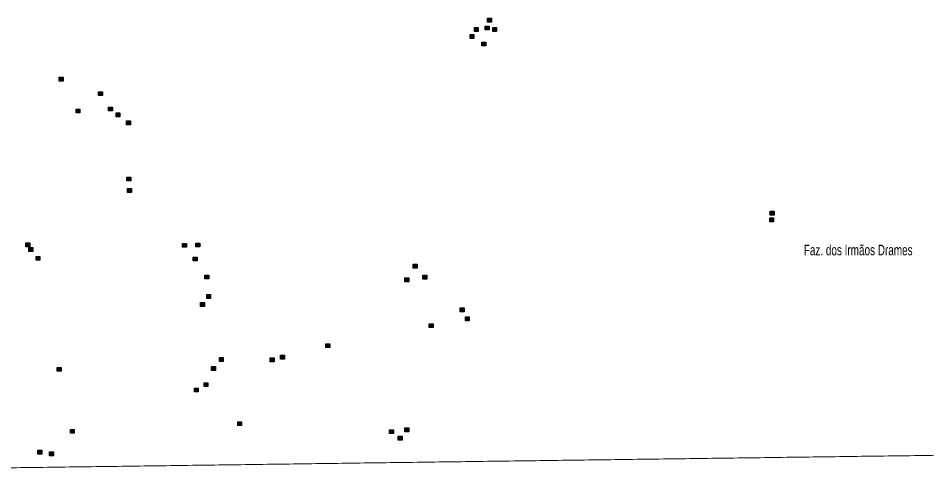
# Model space of a CAD drawing. Extents: x 265.7 to 292.1, y 7676.2 to 7704.2.
# Drawn here: x 272.68 to 279.53, y 7676.18 to 7679.65 of the extents above; entities that cross this region are included whole.
import ezdxf

# ---------------------------------------------------------------- set-up
doc = ezdxf.new("R2010")
doc.units = 0
doc.header["$LTSCALE"] = 0.032
doc.layers.add('2', color=7, linetype='Continuous', lineweight=25)
doc.layers.add('63', color=7, linetype='Continuous', lineweight=13)
doc.layers.add('61', color=7, linetype='Continuous')

msp = doc.modelspace()

# ---------------------------------------------------------------- hatches: boundary and pattern name
at = {"layer": '2'}
for points in [[(276.2203, 7679.6541), (276.2493, 7679.6541), (276.2493, 7679.6251), (276.2203, 7679.6251)], [(276.1216, 7679.5829), (276.1506, 7679.5829), (276.1506, 7679.5539), (276.1216, 7679.5539)], [(276.2036, 7679.5951), (276.2326, 7679.5951), (276.2326, 7679.5661), (276.2036, 7679.5661)], [(276.2597, 7679.5838), (276.2887, 7679.5838), (276.2887, 7679.5548), (276.2597, 7679.5548)], [(276.0885, 7679.5312), (276.1175, 7679.5312), (276.1175, 7679.5022), (276.0885, 7679.5022)], [(276.1781, 7679.474), (276.2071, 7679.474), (276.2071, 7679.445), (276.1781, 7679.445)], [(272.9935, 7679.2092), (273.0225, 7679.2092), (273.0225, 7679.1802), (272.9935, 7679.1802)], [(273.2897, 7679.1003), (273.3187, 7679.1003), (273.3187, 7679.0713), (273.2897, 7679.0713)], [(273.1194, 7678.9688), (273.1484, 7678.9688), (273.1484, 7678.9398), (273.1194, 7678.9398)], [(273.3648, 7678.984), (273.3938, 7678.984), (273.3938, 7678.955), (273.3648, 7678.955)], [(273.4212, 7678.9405), (273.4502, 7678.9405), (273.4502, 7678.9115), (273.4212, 7678.9115)], [(273.5003, 7678.8807), (273.5293, 7678.8807), (273.5293, 7678.8517), (273.5003, 7678.8517)], [(273.5036, 7678.4571), (273.5326, 7678.4571), (273.5326, 7678.4281), (273.5036, 7678.4281)], [(273.5085, 7678.3699), (273.5375, 7678.3699), (273.5375, 7678.3409), (273.5085, 7678.3409)], [(278.3507, 7678.1997), (278.3797, 7678.1997), (278.3797, 7678.1707), (278.3507, 7678.1707)], [(278.3466, 7678.1488), (278.3756, 7678.1488), (278.3756, 7678.1198), (278.3466, 7678.1198)], [(272.7417, 7677.9608), (272.7707, 7677.9608), (272.7707, 7677.9318), (272.7417, 7677.9318)], [(272.7644, 7677.926), (272.7934, 7677.926), (272.7934, 7677.897), (272.7644, 7677.897)], [(273.9225, 7677.9575), (273.9515, 7677.9575), (273.9515, 7677.9285), (273.9225, 7677.9285)], [(274.0224, 7677.9601), (274.0514, 7677.9601), (274.0514, 7677.9311), (274.0224, 7677.9311)], [(272.8184, 7677.8591), (272.8474, 7677.8591), (272.8474, 7677.8301), (272.8184, 7677.8301)], [(274.0032, 7677.8543), (274.0322, 7677.8543), (274.0322, 7677.8253), (274.0032, 7677.8253)], [(275.6609, 7677.801), (275.6899, 7677.801), (275.6899, 7677.772), (275.6609, 7677.772)], [(274.0902, 7677.7187), (274.1192, 7677.7187), (274.1192, 7677.6897), (274.0902, 7677.6897)], [(275.598, 7677.6977), (275.627, 7677.6977), (275.627, 7677.6687), (275.598, 7677.6687)], [(275.7334, 7677.717), (275.7624, 7677.717), (275.7624, 7677.688), (275.7334, 7677.688)], [(274.1049, 7677.5717), (274.1339, 7677.5717), (274.1339, 7677.5427), (274.1049, 7677.5427)], [(274.0579, 7677.5113), (274.0869, 7677.5113), (274.0869, 7677.4823), (274.0579, 7677.4823)], [(276.0145, 7677.4718), (276.0435, 7677.4718), (276.0435, 7677.4428), (276.0145, 7677.4428)], [(276.0531, 7677.4031), (276.0821, 7677.4031), (276.0821, 7677.3741), (276.0531, 7677.3741)], [(275.7811, 7677.3522), (275.8101, 7677.3522), (275.8101, 7677.3232), (275.7811, 7677.3232)], [(275.0022, 7677.2012), (275.0312, 7677.2012), (275.0312, 7677.1722), (275.0022, 7677.1722)], [(274.2001, 7677.0972), (274.2291, 7677.0972), (274.2291, 7677.0682), (274.2001, 7677.0682)], [(274.5827, 7677.0955), (274.6117, 7677.0955), (274.6117, 7677.0665), (274.5827, 7677.0665)], [(274.6602, 7677.1143), (274.6892, 7677.1143), (274.6892, 7677.0853), (274.6602, 7677.0853)], [(272.9782, 7677.023), (273.0072, 7677.023), (273.0072, 7676.994), (272.9782, 7676.994)], [(274.1404, 7677.0294), (274.1694, 7677.0294), (274.1694, 7677.0004), (274.1404, 7677.0004)], [(274.0838, 7676.9073), (274.1128, 7676.9073), (274.1128, 7676.8783), (274.0838, 7676.8783)], [(274.012, 7676.8672), (274.041, 7676.8672), (274.041, 7676.8382), (274.012, 7676.8382)], [(274.338, 7676.6139), (274.367, 7676.6139), (274.367, 7676.5849), (274.338, 7676.5849)], [(273.0774, 7676.5566), (273.1064, 7676.5566), (273.1064, 7676.5276), (273.0774, 7676.5276)], [(275.4825, 7676.5532), (275.5115, 7676.5532), (275.5115, 7676.5242), (275.4825, 7676.5242)], [(275.5979, 7676.5678), (275.6269, 7676.5678), (275.6269, 7676.5388), (275.5979, 7676.5388)], [(275.5478, 7676.5048), (275.5768, 7676.5048), (275.5768, 7676.4758), (275.5478, 7676.4758)], [(272.8321, 7676.3999), (272.8611, 7676.3999), (272.8611, 7676.3709), (272.8321, 7676.3709)], [(272.92, 7676.3861), (272.949, 7676.3861), (272.949, 7676.3571), (272.92, 7676.3571)]]:
    msp.add_hatch(color=256, dxfattribs=at).paths.add_polyline_path(points)

# ---------------------------------------------------------------- linework, layer by layer
for points in [[(276.2203, 7679.6541), (276.2493, 7679.6541), (276.2493, 7679.6251), (276.2203, 7679.6251)], [(276.1216, 7679.5829), (276.1506, 7679.5829), (276.1506, 7679.5539), (276.1216, 7679.5539)], [(276.2036, 7679.5951), (276.2326, 7679.5951), (276.2326, 7679.5661), (276.2036, 7679.5661)], [(276.2597, 7679.5838), (276.2887, 7679.5838), (276.2887, 7679.5548), (276.2597, 7679.5548)], [(276.0885, 7679.5312), (276.1175, 7679.5312), (276.1175, 7679.5022), (276.0885, 7679.5022)], [(276.1781, 7679.474), (276.2071, 7679.474), (276.2071, 7679.445), (276.1781, 7679.445)], [(272.9935, 7679.2092), (273.0225, 7679.2092), (273.0225, 7679.1802), (272.9935, 7679.1802)], [(273.2897, 7679.1003), (273.3187, 7679.1003), (273.3187, 7679.0713), (273.2897, 7679.0713)], [(273.1194, 7678.9688), (273.1484, 7678.9688), (273.1484, 7678.9398), (273.1194, 7678.9398)], [(273.3648, 7678.984), (273.3938, 7678.984), (273.3938, 7678.955), (273.3648, 7678.955)], [(273.4212, 7678.9405), (273.4502, 7678.9405), (273.4502, 7678.9115), (273.4212, 7678.9115)], [(273.5003, 7678.8807), (273.5293, 7678.8807), (273.5293, 7678.8517), (273.5003, 7678.8517)], [(273.5036, 7678.4571), (273.5326, 7678.4571), (273.5326, 7678.4281), (273.5036, 7678.4281)], [(273.5085, 7678.3699), (273.5375, 7678.3699), (273.5375, 7678.3409), (273.5085, 7678.3409)], [(278.3507, 7678.1997), (278.3797, 7678.1997), (278.3797, 7678.1707), (278.3507, 7678.1707)], [(278.3466, 7678.1488), (278.3756, 7678.1488), (278.3756, 7678.1198), (278.3466, 7678.1198)], [(272.7417, 7677.9608), (272.7707, 7677.9608), (272.7707, 7677.9318), (272.7417, 7677.9318)], [(272.7644, 7677.926), (272.7934, 7677.926), (272.7934, 7677.897), (272.7644, 7677.897)], [(273.9225, 7677.9575), (273.9515, 7677.9575), (273.9515, 7677.9285), (273.9225, 7677.9285)], [(274.0224, 7677.9601), (274.0514, 7677.9601), (274.0514, 7677.9311), (274.0224, 7677.9311)], [(272.8184, 7677.8591), (272.8474, 7677.8591), (272.8474, 7677.8301), (272.8184, 7677.8301)], [(274.0032, 7677.8543), (274.0322, 7677.8543), (274.0322, 7677.8253), (274.0032, 7677.8253)], [(275.6609, 7677.801), (275.6899, 7677.801), (275.6899, 7677.772), (275.6609, 7677.772)], [(274.0902, 7677.7187), (274.1192, 7677.7187), (274.1192, 7677.6897), (274.0902, 7677.6897)], [(275.598, 7677.6977), (275.627, 7677.6977), (275.627, 7677.6687), (275.598, 7677.6687)], [(275.7334, 7677.717), (275.7624, 7677.717), (275.7624, 7677.688), (275.7334, 7677.688)], [(274.1049, 7677.5717), (274.1339, 7677.5717), (274.1339, 7677.5427), (274.1049, 7677.5427)], [(274.0579, 7677.5113), (274.0869, 7677.5113), (274.0869, 7677.4823), (274.0579, 7677.4823)], [(276.0145, 7677.4718), (276.0435, 7677.4718), (276.0435, 7677.4428), (276.0145, 7677.4428)], [(276.0531, 7677.4031), (276.0821, 7677.4031), (276.0821, 7677.3741), (276.0531, 7677.3741)], [(275.7811, 7677.3522), (275.8101, 7677.3522), (275.8101, 7677.3232), (275.7811, 7677.3232)], [(275.0022, 7677.2012), (275.0312, 7677.2012), (275.0312, 7677.1722), (275.0022, 7677.1722)], [(274.2001, 7677.0972), (274.2291, 7677.0972), (274.2291, 7677.0682), (274.2001, 7677.0682)], [(274.5827, 7677.0955), (274.6117, 7677.0955), (274.6117, 7677.0665), (274.5827, 7677.0665)], [(274.6602, 7677.1143), (274.6892, 7677.1143), (274.6892, 7677.0853), (274.6602, 7677.0853)], [(272.9782, 7677.023), (273.0072, 7677.023), (273.0072, 7676.994), (272.9782, 7676.994)], [(274.1404, 7677.0294), (274.1694, 7677.0294), (274.1694, 7677.0004), (274.1404, 7677.0004)], [(274.0838, 7676.9073), (274.1128, 7676.9073), (274.1128, 7676.8783), (274.0838, 7676.8783)], [(274.012, 7676.8672), (274.041, 7676.8672), (274.041, 7676.8382), (274.012, 7676.8382)], [(274.338, 7676.6139), (274.367, 7676.6139), (274.367, 7676.5849), (274.338, 7676.5849)], [(273.0774, 7676.5566), (273.1064, 7676.5566), (273.1064, 7676.5276), (273.0774, 7676.5276)], [(275.4825, 7676.5532), (275.5115, 7676.5532), (275.5115, 7676.5242), (275.4825, 7676.5242)], [(275.5979, 7676.5678), (275.6269, 7676.5678), (275.6269, 7676.5388), (275.5979, 7676.5388)], [(275.5478, 7676.5048), (275.5768, 7676.5048), (275.5768, 7676.4758), (275.5478, 7676.4758)], [(272.8321, 7676.3999), (272.8611, 7676.3999), (272.8611, 7676.3709), (272.8321, 7676.3709)], [(272.92, 7676.3861), (272.949, 7676.3861), (272.949, 7676.3571), (272.92, 7676.3571)]]:
    msp.add_lwpolyline(points, close=True, dxfattribs=at)
at = {"layer": '63'}
msp.add_spline([(266.1055, 7676.1764), (266.6361, 7676.1838), (267.1667, 7676.1913), (267.6972, 7676.1987), (268.2278, 7676.2061), (268.7584, 7676.2135), (269.2889, 7676.2209), (269.8195, 7676.2283), (270.3501, 7676.2356), (270.8806, 7676.2429), (271.4112, 7676.2502), (271.9418, 7676.2575), (272.4723, 7676.2648), (273.0029, 7676.2721), (273.5335, 7676.2793), (274.064, 7676.2865), (274.5946, 7676.2937), (275.1251, 7676.3009), (275.6557, 7676.3081), (276.1862, 7676.3153), (276.7168, 7676.3224), (277.2473, 7676.3295), (277.7779, 7676.3366), (278.3084, 7676.3437), (278.839, 7676.3508), (279.3695, 7676.3578), (279.9, 7676.3649), (280.4306, 7676.3719), (280.9611, 7676.3789), (281.4917, 7676.3859), (282.0222, 7676.3929), (282.5527, 7676.3998), (283.0833, 7676.4067), (283.6138, 7676.4137), (284.1443, 7676.4206), (284.6749, 7676.4275), (285.2054, 7676.4343), (285.7359, 7676.4412), (286.2665, 7676.448), (286.797, 7676.4548), (287.3275, 7676.4616), (287.858, 7676.4684), (288.3886, 7676.4752), (288.9191, 7676.4819), (289.4496, 7676.4887), (289.9801, 7676.4954), (290.5106, 7676.5021), (291.0411, 7676.5087), (291.5717, 7676.5154), (292.1022, 7676.5221)], degree=3, dxfattribs=at)

# ---------------------------------------------------------------- texts
at = {"layer": '61', "width": 0.7}
msp.add_text('Faz. dos Irmãos Drames', height=0.08, dxfattribs=at).set_placement((278.6031, 7677.8674))

doc.saveas('drawing.dxf')
